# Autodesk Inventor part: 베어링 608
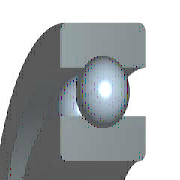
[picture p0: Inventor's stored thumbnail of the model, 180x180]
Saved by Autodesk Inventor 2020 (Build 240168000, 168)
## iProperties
Created: 2012-02
Part Number: 베어링 608
Material: 강철, 연강
Description: 깊은 그루브 볼 베어링
Document SubType Name: Modeling
Standard: KS B 2023
Designer: mduedu
Standards Organization: KS
Language: ko-KR
Size Designation: 608 - 8 x 22 x 7
Categories: <MemberInstance><Categories><Category DisplayName="샤프트 부품" InternalName="7f7aeb1f-a693-4053-b835-cee3144e0d98" Mnemonic="SHFT"><Category DisplayName="베어링" Inter
Density: 1 g/cm^3
Appearance: 노란색
IsCustomPart: 1
Author: mduedu
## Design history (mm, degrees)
sketch "스케치" dims "d0" = 3.64 (= -0.26 x WD + 0.26 x BD)
  geometry: L1 (1.68, 7.5)-(5.32, 7.5); L2 (3.5, 7.5)-(3.5, 5.68); L3 (3.5, 7.5)-(3.5, 9.32); L4 (2.148, 6.282)-(0, 6.282); L5 (0, 4)-(7, 4); L6 (2.148, 8.718)-(0, 8.718); L7 (0, 11)-(7, 11); L8 (7, 4)-(7, 6.282); L9 (4.852, 6.282)-(7, 6.282); L10 (4.852, 8.718)-(7, 8.718); L11 (7, 11)-(7, 8.718); L12 (-1.4, 0)-(8.4, 0) reference; L13 (0, -0.3)-(0, 5.3) reference
  constraints: 22 end point, 4 point on line, 2 collinear, 2 perpendicular, 2 symmetric about line, 1 midpoint, 1 parallel, 14 other
  dimensions: "d9" = 8 diameter of L5 L12 (= WD); "d11" = 22 diameter of L7 L12 (= BD); "d12" = 7 distance between parallel lines of L8 L13 (= KB); "d13" = 12.564 diameter of L9 L12 (= 0.326 x BD + 0.674 x WD)
revolve "본체" stored, may be unused: angle "d6" = 90 deg
revolve "볼" stored, may be unused: angle "d7" = 90 deg
pattern_circular "IDS_ARRAYBALL[SIMPL:T]" dims angle "d3" = 360 deg
body "Solid1"
fillet "모깎기1" dims "d1" = 0.3 (= KRS)
other parameters: "WD" = 8 [user parameter; used in 5 equation terms], "BD" = 22 [user parameter; used in 5 equation terms], "KB" = 7 [user parameter; used in 1 equation term], "KRS" = 0.3 [user parameter; used in 1 equation term], "d4" = 0, "d5" = 0, "d8" = 0, "d14" = 0, "d15" = 0, "BBA" = 0 [user parameter], "BC0" = 1370000 [user parameter], "BC" = 3250000 [user parameter], "BR" = 11 (= 0.5 x BD) [user parameter], "WR" = 4 (= 0.5 x WD) [user parameter]
